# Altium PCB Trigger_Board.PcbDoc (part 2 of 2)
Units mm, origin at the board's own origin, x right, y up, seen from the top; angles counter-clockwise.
Board outline 80 x 80 mm, 4 copper layers (Component Side, Signal Layer 1, Signal Layer 2, Bottom Layer), stack 0.651 mm thick; 190 components, 73 nets, 468 pads, 398 vias.
Unrouted connection lines stored in the file: 444.
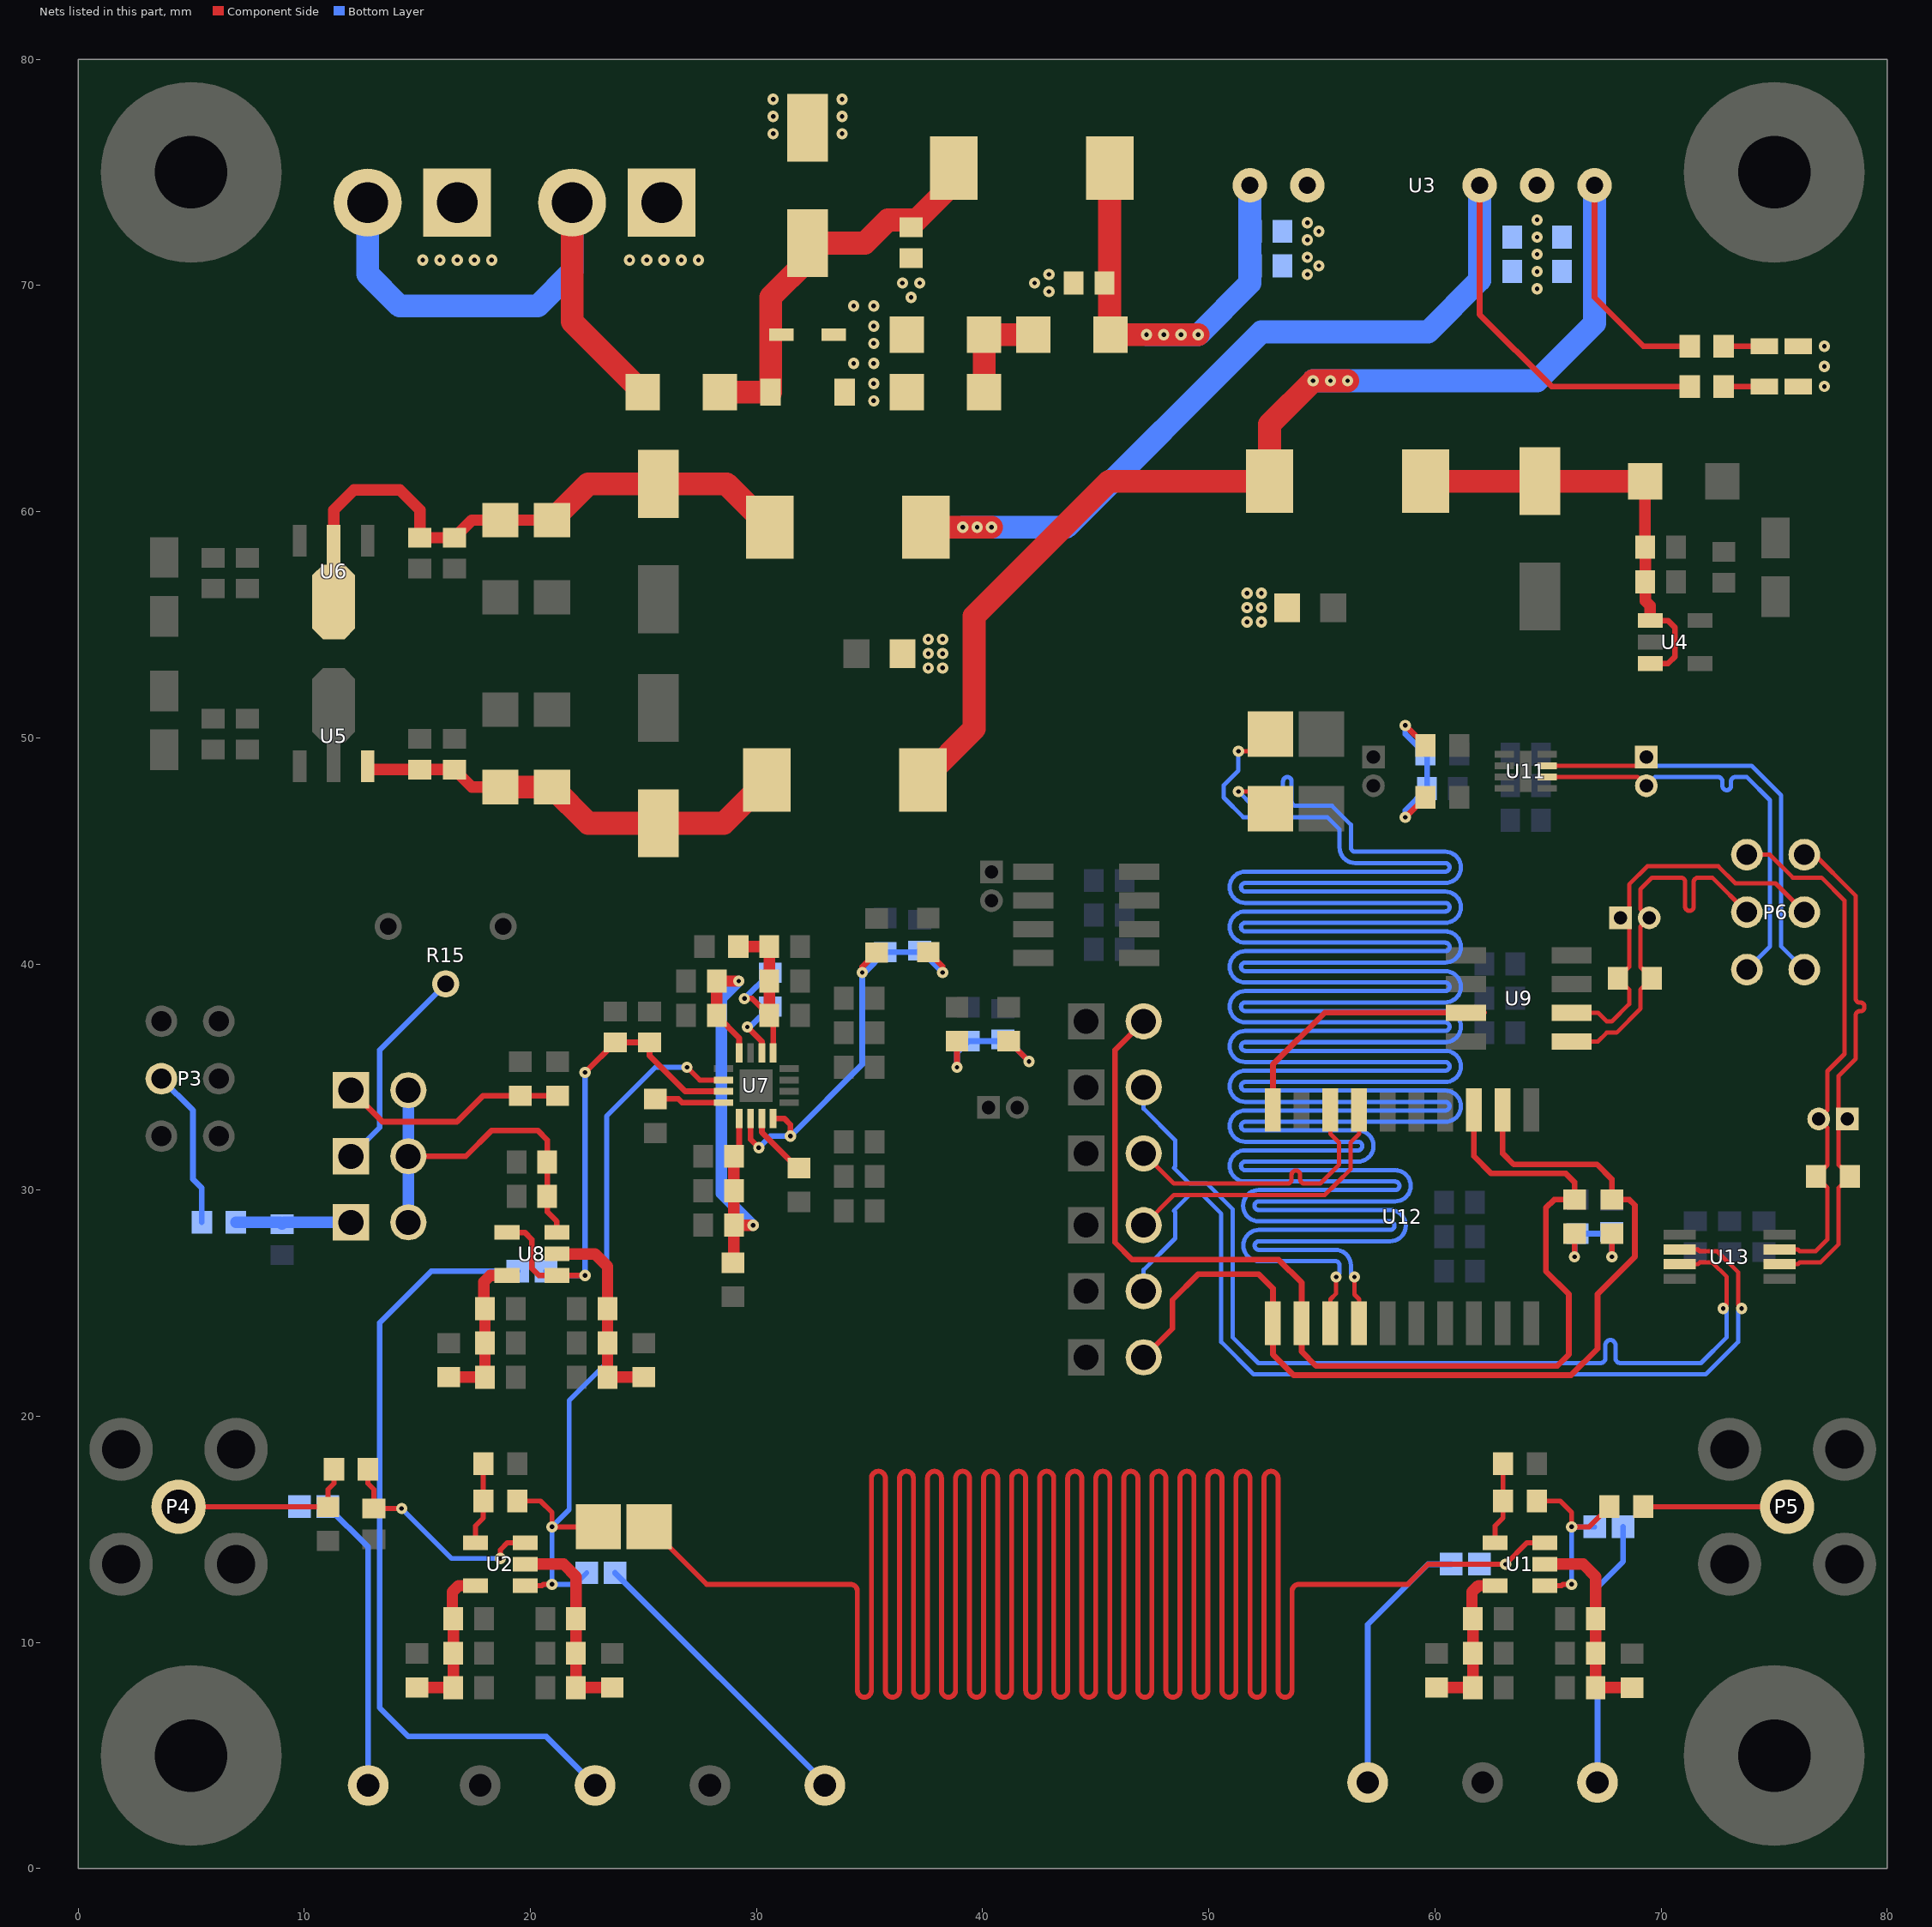
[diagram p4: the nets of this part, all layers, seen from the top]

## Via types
v1: diameter 0.5, hole 0.2, Component Side to Bottom Layer, 398 vias

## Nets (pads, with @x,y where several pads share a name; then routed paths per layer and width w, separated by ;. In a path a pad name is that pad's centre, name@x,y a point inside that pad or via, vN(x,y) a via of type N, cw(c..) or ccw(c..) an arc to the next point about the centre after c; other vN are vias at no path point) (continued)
DIn_N: J17.1 U12.4 | length 198.8
  Component Side w0.19: v1(51.308,47.625) 51.961,47.625 J17.1@52.723,46.863 ; v1(56.436,26.162) 56.436,25.381 56.642,25.174 U12.4@56.642,24.117
  Bottom Layer w0.19: v1(51.308,47.625) 51.943,46.99 53.213,46.99 ccw(c53.213,47.056) 53.279,47.056 53.279,48.073 cw(c53.469,48.073) 53.469,48.263 cw(c53.469,48.073) 53.659,48.073 53.659,47.18 ccw(c53.849,47.18) 53.849,46.99 54.039,46.99 54.229,46.99 55.444,46.99 56.281,46.153 56.281,45.15 ccw(c56.471,45.15) 56.471,44.96 60.452,44.96 cw(c60.452,44.27) 61.142,44.27 cw(c60.452,44.27) 60.452,43.58 51.61,43.58 ccw(c51.61,43.39) 51.42,43.39 ccw(c51.61,43.39) 51.61,43.2 60.452,43.2 cw(c60.452,42.51) 61.142,42.51 cw(c60.452,42.51) 60.452,41.82 51.61,41.82 ccw(c51.61,41.63) 51.42,41.63 ccw(c51.61,41.63) 51.61,41.44 60.452,41.44 cw(c60.452,40.75) 61.142,40.75 cw(c60.452,40.75) 60.452,40.06 51.61,40.06 ccw(c51.61,39.87) 51.42,39.87 ccw(c51.61,39.87) 51.61,39.68 60.452,39.68 cw(c60.452,38.99) 61.142,38.99 cw(c60.452,38.99) 60.452,38.3 51.61,38.3 ccw(c51.61,38.11) 51.42,38.11 ccw(c51.61,38.11) 51.61,37.92 60.452,37.92 cw(c60.452,37.23) 61.142,37.23 cw(c60.452,37.23) 60.452,36.54 51.61,36.54 ccw(c51.61,36.35) 51.42,36.35 ccw(c51.61,36.35) 51.61,36.16 60.452,36.16 cw(c60.452,35.47) 61.142,35.47 cw(c60.452,35.47) 60.452,34.78 51.61,34.78 ccw(c51.61,34.59) 51.42,34.59 ccw(c51.61,34.59) 51.61,34.4 60.452,34.4 cw(c60.452,33.71) 61.142,33.71 cw(c60.452,33.71) 60.452,33.02 51.61,33.02 ccw(c51.61,32.83) 51.42,32.83 ccw(c51.61,32.83) 51.61,32.64 56.59,32.64 cw(c56.59,31.95) 57.28,31.95 cw(c56.59,31.95) 56.59,31.26 51.61,31.26 ccw(c51.61,31.07) 51.42,31.07 ccw(c51.61,31.07) 51.61,30.88 58.233,30.88 cw(c58.233,30.19) 58.923,30.19 cw(c58.233,30.19) 58.233,29.5 52.205,29.5 ccw(c52.205,29.31) 52.015,29.31 ccw(c52.205,29.31) 52.205,29.12 58.016,29.12 cw(c58.016,28.43) 58.706,28.43 cw(c58.016,28.43) 58.016,27.74 52.215,27.74 ccw(c52.215,27.55) 52.025,27.55 ccw(c52.215,27.55) 52.215,27.36 55.591,27.36 cw(c55.591,26.67) 56.281,26.67 56.281,26.317 v1(56.436,26.162)
DIn_P: J14.1 U12.3 | length 198.8
  Component Side w0.19: v1(51.308,49.403) 51.961,49.403 J14.1@52.723,50.165 ; U12.3@55.372,24.117 55.372,25.174 55.626,25.428 v1(55.626,26.162)
  Bottom Layer w0.19: v1(51.308,49.403) 51.308,48.551 50.653,47.896 50.653,47.354 51.517,46.49 55.237,46.49 55.781,45.946 55.781,45.15 ccw(c56.471,45.15) 56.471,44.46 60.452,44.46 cw(c60.452,44.27) 60.642,44.27 cw(c60.452,44.27) 60.452,44.08 51.61,44.08 ccw(c51.61,43.39) 50.92,43.39 ccw(c51.61,43.39) 51.61,42.7 60.452,42.7 cw(c60.452,42.51) 60.642,42.51 cw(c60.452,42.51) 60.452,42.32 51.61,42.32 ccw(c51.61,41.63) 50.92,41.63 ccw(c51.61,41.63) 51.61,40.94 60.452,40.94 cw(c60.452,40.75) 60.642,40.75 cw(c60.452,40.75) 60.452,40.56 51.61,40.56 ccw(c51.61,39.87) 50.92,39.87 ccw(c51.61,39.87) 51.61,39.18 60.452,39.18 cw(c60.452,38.99) 60.642,38.99 cw(c60.452,38.99) 60.452,38.8 51.61,38.8 ccw(c51.61,38.11) 50.92,38.11 ccw(c51.61,38.11) 51.61,37.42 60.452,37.42 cw(c60.452,37.23) 60.642,37.23 cw(c60.452,37.23) 60.452,37.04 51.61,37.04 ccw(c51.61,36.35) 50.92,36.35 ccw(c51.61,36.35) 51.61,35.66 60.452,35.66 cw(c60.452,35.47) 60.642,35.47 cw(c60.452,35.47) 60.452,35.28 51.61,35.28 ccw(c51.61,34.59) 50.92,34.59 ccw(c51.61,34.59) 51.61,33.9 60.452,33.9 cw(c60.452,33.71) 60.642,33.71 cw(c60.452,33.71) 60.452,33.52 51.61,33.52 ccw(c51.61,32.83) 50.92,32.83 ccw(c51.61,32.83) 51.61,32.14 56.59,32.14 cw(c56.59,31.95) 56.78,31.95 cw(c56.59,31.95) 56.59,31.76 51.61,31.76 ccw(c51.61,31.07) 50.92,31.07 ccw(c51.61,31.07) 51.61,30.38 58.233,30.38 cw(c58.233,30.19) 58.423,30.19 cw(c58.233,30.19) 58.233,30 52.205,30 ccw(c52.205,29.31) 51.515,29.31 ccw(c52.205,29.31) 52.205,28.62 58.016,28.62 cw(c58.016,28.43) 58.206,28.43 cw(c58.016,28.43) 58.016,28.24 52.215,28.24 ccw(c52.215,27.55) 51.525,27.55 ccw(c52.215,27.55) 52.215,26.86 55.591,26.86 cw(c55.591,26.67) 55.781,26.67 55.781,26.317 v1(55.626,26.162)
DOut_N: J12.2 U12.17 | length 12.9
  Component Side w0.19: J12.2@47.117,28.448 48.455,29.786 55.131,29.786 55.658,30.313 56.257,30.912 56.257,32.099 56.642,32.484 U12.17@56.642,33.541
DOut_P: J13.2 U12.18 | length 12.9
  Component Side w0.19: J13.2@47.117,31.623 48.455,30.285 53.467,30.285 ccw(c53.467,30.475) 53.657,30.475 53.657,30.673 cw(c53.847,30.673) 53.847,30.863 cw(c53.847,30.673) 54.037,30.673 54.037,30.475 ccw(c54.227,30.475) 54.227,30.285 54.923,30.285 55.757,31.119 55.757,32.099 55.372,32.484 U12.18@55.372,33.541
EXT_threshold: C72.2 J8.1 L12.2 | length 5.2
  Bottom Layer w0.508: L12.2@6.973,28.575 8.935,28.575 C72.2@9.017,28.493 9.099,28.575 J8.1@12.065,28.575
Full_N: P6.6 R23.2 TP14.2 U13.3 | length 23.5
  Component Side w0.19: P6.6@73.787,44.831 74.803,44.831 75.819,43.815 77.089,43.815 78.105,42.799 78.105,36.017 77.347,35.259 77.347,33.532 TP14.2@76.962,33.147 77.347,32.762 77.347,31.107 R23.2@76.847,30.607 77.347,30.107 77.347,27.817 76.831,27.301 76.119,27.301 76.044,27.376 U13.3@75.237,27.376
Full_P: P6.5 R23.1 TP14.1 U13.2 | length 22.6
  Component Side w0.19: U13.2@75.237,26.726 76.044,26.726 76.119,26.801 77.038,26.801 77.189,26.951 77.847,27.61 77.847,30.107 R23.1@78.347,30.607 77.847,31.107 77.847,33.147 77.847,35.052 78.605,35.81 78.605,37.719 78.605,37.74 cw(c78.776,37.74) 78.776,37.911 78.816,37.911 ccw(c78.816,38.082) 78.987,38.082 78.987,38.12 ccw(c78.816,38.12) 78.816,38.291 78.776,38.291 cw(c78.776,38.462) 78.605,38.462 78.605,38.481 78.605,43.006 78.459,43.153 76.78,44.831 P6.5@76.327,44.831
GND: C14.1 C15.1 C27.2 C28.2 D3.2 D4.1 R9.1 R10.1 U3.6
  other v1: 37.592,53.086 38.227,53.086 37.592,53.721 38.227,53.721 37.592,54.356 38.227,54.356 51.689,55.118 52.324,55.118 51.689,55.753 52.324,55.753 51.689,56.388 52.324,56.388 77.216,65.532 77.216,66.421 77.216,67.31 64.516,69.85 64.516,70.612 64.516,71.374 64.516,72.136 64.516,72.898
HYS: R21.1 U7.14 | length 2.8
  Component Side w0.254: v1(29.591,37.211) 30.234,36.568 U7.14@30.234,36.068
  Bottom Layer w0.254: v1(29.591,37.211) 29.706,37.211 R21.1@30.607,38.112
IGND: C16.2 C17.1 C18.1 C19.1 C20.1 C29.1 C30.1 D1.1 D2.1 P1.1 P2.1 U3.2
  other v1: 35.179,64.897 35.179,65.659 34.29,66.548 35.179,66.548 35.179,67.437 35.179,68.199 34.29,69.088 35.179,69.088 36.83,69.469 42.926,69.723 36.449,70.104 37.211,70.104 42.291,70.104 42.926,70.485 54.356,70.485 54.864,70.866 15.24,71.12 16.002,71.12 16.764,71.12 17.526,71.12 18.288,71.12 24.384,71.12 25.146,71.12 25.908,71.12 26.67,71.12 27.432,71.12 54.356,71.247 54.356,72.009 54.864,72.39 54.356,72.771 30.734,76.708 33.782,76.708 30.734,77.47 33.782,77.47 30.734,78.232 33.782,78.232
LogD0_N: J10.2 R29.1 U12.1 U12.12 | length 42.6
  Component Side w0.254: J10.2@47.117,22.606 48.387,23.876 48.387,25.146 49.53,26.289 52.197,26.289 52.832,25.654 U12.1@52.832,24.117 52.832,22.733 53.744,21.821 66.017,21.821 67.183,22.987 67.183,25.4 68.834,27.051 68.834,29.337 68.592,29.579 R29.1@67.818,29.579 67.818,30.48 67.16,31.138 63.477,31.138 62.992,31.623 U12.12@62.992,33.541
LogD0_P: J11.2 R28.1 U12.2 U12.13 | length 50.7
  Component Side w0.254: J11.2@47.117,37.465 45.847,36.195 45.847,27.686 46.609,26.924 53.086,26.924 54.102,25.908 U12.2@54.102,24.117 54.102,22.86 54.737,22.225 65.405,22.225 65.913,22.733 65.913,25.4 64.897,26.416 64.897,29.21 65.266,29.579 R28.1@66.167,29.579 66.167,30.353 65.786,30.734 62.484,30.734 61.722,31.496 U12.13@61.722,33.541
NetC1_1: C1.1 C3.1 C5.1 L1.1 U1.5 | length 7
  Component Side w0.508: L1.1@60.071,8.013 60.083,8.001 C1.1@61.677,8.001 C3.1@61.677,9.525 C5.1@61.677,11.049 ; C5.1@61.632,11.049 61.632,12.229 61.915,12.512 U1.5@62.654,12.512
NetC2_1: C2.1 C4.1 C6.1 L2.1 U2.5 | length 6.9
  Component Side w0.508: L2.1@15.031,8.013 C2.1@16.58,8.013 ; C6.1@16.547,11.049 16.547,12.229 16.83,12.512 U2.5@17.569,12.512 ; C2.1@16.592,8.001 C4.1@16.592,9.525 C6.1@16.592,11.049
NetC7_1: C7.1 C9.1 C10.1 L3.2 U2.2 | length 9
  Component Side w0.508: U2.2@19.769,13.462 21.463,13.462 22.016,12.909 C7.1@22.016,11.049 C9.1@22.016,9.525 C10.1@22.016,8.001 23.61,8.001 L3.2@23.622,8.013
NetC8_2: C8.2 R3.2 U2.3 | length 10
  Component Side w0.22: R3.2@12.815,17.653 12.815,17.03 13.081,16.764 C8.2@13.081,15.92 v1(14.306,15.92) ; v1(18.669,13.716) 18.669,14.097 18.984,14.412 U2.3@19.769,14.412
  Bottom Layer w0.22: v1(14.306,15.92) 16.51,13.716 v1(18.669,13.716)
NetC11_1: C11.1 C12.1 C13.1 L4.2 U1.2 | length 9
  Component Side w0.508: U1.2@64.854,13.462 66.548,13.462 67.101,12.909 C11.1@67.101,11.049 C12.1@67.101,9.525 C13.1@67.101,8.001 L4.2@68.707,8.001
NetC16_1: C16.1 C17.2 D1.2 D2.2 F1.2 L5.1 | length 17.7
  Component Side w1.016: F1.2@28.38,65.278 D1.2@30.623,65.278 30.623,67.818 30.623,69.485 32.258,71.12 C16.1@32.258,71.872 34.788,71.872 35.814,72.898 36.83,72.898 37.084,72.898 38.714,74.528 L5.1@38.714,75.184
NetC18_2: C18.2 C19.2 C20.2 L5.2 R8.2 U3.1 | length 20.8
  Component Side w1.016: L5.2@45.614,75.184 45.614,70.104 45.614,68.11 R8.2@45.652,68.072 ; R8.2@45.652,67.818 v1(47.244,67.818) v1(48.006,67.818) v1(48.768,67.818) v1(49.53,67.818)
  Bottom Layer w1.016: v1(47.244,67.818) v1(48.006,67.818) v1(48.768,67.818) v1(49.53,67.818) 51.816,70.104 51.816,70.866 51.816,72.39 U3.1@51.816,74.422
NetC21_1: C21.1 C22.2 C23.2 C24.2 L6.2 U4.1 U4.3 | length 19.7
  Component Side w0.254: U4.3@69.512,53.279 70.297,53.279 70.612,53.594 70.612,54.864 70.297,55.179 U4.1@69.512,55.179
  Component Side w0.508: C22.2@69.283,61.341 69.283,58.434 C23.2@69.297,58.42 C24.2@69.297,56.896 69.297,56.052 69.512,55.837 U4.1@69.512,55.179
  Component Side w1.016: L6.2@59.584,61.341 64.643,61.341 C22.2@69.283,61.341
NetC29_2: C29.2 C30.2 R8.1 | length 4.7
  Component Side w1.016: C29.2@40.064,65.278 C30.2@40.064,67.818 R8.1@42.232,67.818
NetC31_1: C31.1 C32.2 C33.2 C34.2 C35.2 L7.2 U5.3 | length 19.5
  Component Side w0.508: U5.3@12.803,48.735 12.942,48.596 C35.2@15.113,48.596 C34.2@16.637,48.596 17.413,47.82 C33.2@18.669,47.82
  Component Side w1.016: C33.2@18.669,47.82 C32.2@20.955,47.82 22.557,46.218 C31.1@25.654,46.218 28.544,46.218 L7.2@30.459,48.133
NetC39_2: C39.2 C40.2 C41.2 C42.2 C43.2 L8.2 U6.2 | length 24.6
  Component Side w0.508: U6.2@11.303,58.507 11.303,60.071 12.192,60.96 14.224,60.96 15.113,60.071 C43.2@15.113,58.846 C42.2@16.637,58.846 17.413,59.622 C41.2@18.669,59.622 C40.2@20.955,59.622
  Component Side w1.016: C40.2@20.955,59.622 22.557,61.224 C39.2@25.654,61.224 28.671,61.224 L8.2@30.586,59.309
NetC47_1: C47.1 C48.1 C49.1 L9.1 U8.5 | length 7
  Component Side w0.508: L9.1@16.383,21.729 17.977,21.729 C47.1@17.989,21.717 C48.1@17.989,23.241 17.989,24.72 17.966,24.743 17.944,24.765 17.944,25.945 18.227,26.228 U8.5@18.966,26.228
NetC52_1: C52.1 C53.1 C57.1 L10.2 U8.2 | length 9
  Component Side w0.508: U8.2@21.166,27.178 22.86,27.178 23.413,26.625 C52.1@23.413,24.765 C53.1@23.413,23.241 C57.1@23.413,21.717 23.425,21.729 L10.2@25.019,21.729
NetC54_2: C54.2 R17.2 R18.2 R20.1 U7.6 U7.8 | length 19.7
  Component Side w0.254: U7.6@29.734,33.168 29.734,32.242 v1(30.099,31.877) ; U7.8@30.734,33.168 31.221,33.168 31.496,32.893 v1(31.496,32.385) ; v1(34.671,39.624) 34.671,39.872 R17.2@35.306,40.507 ; R18.2@37.592,40.525 38.227,39.89 v1(38.227,39.624)
  Bottom Layer w0.254: v1(30.099,31.877) 30.607,32.385 v1(31.496,32.385) 34.671,35.56 v1(34.671,39.624) 34.786,39.624 R20.1@35.687,40.525 37.141,40.525 C54.2@37.211,40.595 37.256,40.595 v1(38.227,39.624)
NetC55_2: C55.2 C56.2 J6.2 J7.2 J8.2 U8.3 | length 16.9
  Component Side w0.254: J7.2@14.605,31.496 17.145,31.496 18.288,32.639 20.32,32.639 20.746,32.213 C55.2@20.746,31.242 C56.2@20.746,29.718 20.746,29.038 21.166,28.618 U8.3@21.166,28.128
  Bottom Layer w0.508: J8.2@14.605,28.575 J7.2@14.605,31.496 J6.2@14.605,34.417
NetC59_1: C59.1 C61.1 C63.1 C65.1 C67.1 L11.1 U7.5 U7.16 | length 23.6
  Component Side w0.254: C67.1@28.239,37.719 29.234,36.724 U7.16@29.234,36.068 ; C63.1@29.001,31.496 29.234,31.729 U7.5@29.234,33.168
  Component Side w0.508: C67.1@28.239,37.719 C65.1@28.239,39.243 v1(29.21,39.243) ; L11.1@28.956,26.785 29.001,26.83 C59.1@29.001,28.448 ; C63.1@29.001,31.496 C61.1@29.001,29.972 C59.1@29.001,28.448 ; v1(29.845,28.448) C59.1@29.001,28.448
  Bottom Layer w0.508: v1(29.21,39.243) 28.448,38.481 28.448,29.845 v1(29.845,28.448)
NetC69_1: C69.1 C70.1 C71.1 L13.2 R21.2 U7.13 | length 9.4
  Component Side w0.254: v1(29.464,38.469) 29.812,38.469 C69.1@30.562,37.719 30.734,37.547 U7.13@30.734,36.068 ; C69.1@30.734,37.637 C69.1@30.816,37.719
  Component Side w0.508: L13.2@29.198,40.767 C71.1@30.562,40.767 C70.1@30.562,39.243 C69.1@30.562,37.719
  Bottom Layer w0.254: v1(29.464,38.469) R21.2@30.607,39.612
  Bottom Layer w0.508: R21.2@30.468,39.612 R21.2@30.607,39.612
NetC88_2: C88.2 R24.2 R25.2 R30.1 | length 7.4
  Component Side w0.254: v1(58.686,46.482) R25.2@59.575,47.371 ; v1(58.686,50.546) R24.2@59.575,49.657
  Bottom Layer w0.254: v1(58.686,46.482) 58.686,46.793 C88.2@59.645,47.752 59.645,49.206 R30.1@59.575,49.276 58.686,50.165 v1(58.686,50.546)
NetC89_2: C89.2 R26.2 R27.2 R31.1 | length 6.9
  Component Side w0.254: v1(38.862,35.433) R26.2@38.862,36.588 ; R27.2@41.148,36.588 v1(42.049,35.687)
  Bottom Layer w0.254: v1(38.862,35.433) 38.862,36.08 R31.1@39.37,36.588 40.697,36.588 40.767,36.658 C89.2@40.894,36.658 41.078,36.658 v1(42.049,35.687)
NetC90_2: C90.2 R28.2 R29.2 R32.1 | length 5.8
  Component Side w0.254: v1(66.167,27.051) R28.2@66.167,28.079 ; v1(67.818,27.051) R29.2@67.818,28.079
  Bottom Layer w0.254: v1(66.167,27.051) 66.167,27.952 R32.1@66.294,28.079 67.748,28.079 C90.2@67.818,28.149 v1(67.818,27.051)
NetD3_1: D3.1 R11.2 | length 1.8
  Component Side w0.254: R11.2@72.759,67.31 D3.1@74.561,67.31
NetD4_2: D4.2 R12.2 | length 1.8
  Component Side w0.254: R12.2@72.759,65.532 D4.2@74.561,65.532
NetF1_1: F1.1 P1.2 P2.2 | length 26.1
  Component Side w1.016: P2.2@21.844,73.66 21.844,68.394 F1.1@24.96,65.278
  Bottom Layer w1.016: P1.2@12.804,73.66 12.804,70.508 14.224,69.088 20.32,69.088 21.844,70.612 P2.2@21.844,73.66
NetJ1_1: J1.1 J4.1 R1.2 U2.1 U7.2 | length 35.7
  Component Side w0.22: R1.2@19.48,16.195 R1.2@19.419,16.256 20.447,16.256 20.955,15.748 v1(20.955,15.113) J4.1@23.005,15.113 ; U2.1@19.83,12.573 U2.1@19.769,12.512 20.513,12.512 20.574,12.573 v1(20.955,12.573) ; v1@27.051,35.433 v1(26.924,35.433) 27.489,34.868 U7.2@28.534,34.868
  Bottom Layer w0.22: J1.1@22.489,13.081 21.981,12.573 v1(20.955,12.573) v1(20.955,15.113) 21.717,15.875 21.717,20.701 23.368,22.352 23.368,33.274 25.527,35.433 v1(26.924,35.433)
NetJ1_2: J1.2 TP1.1 | length 13.2
  Bottom Layer w0.254: J1.2@23.739,13.081 33.02,3.8 TP1.1@33.02,3.683
NetJ2_1: J2.1 J4.2 U1.3 | length 343.8
  Component Side w0.22: J4.2@25.255,15.113 27.795,12.573 33.274,12.573 33.528,12.573 33.838,12.573 34.148,12.573 cw(c34.148,12.263) 34.458,12.263 34.458,7.887 ccw(c34.768,7.887) 34.768,7.577 ccw(c34.768,7.887) 35.078,7.887 35.078,12.573 35.078,17.259 cw(c35.388,17.259) 35.388,17.569 cw(c35.388,17.259) 35.698,17.259 35.698,12.573 35.698,7.887 ccw(c36.008,7.887) 36.008,7.577 ccw(c36.008,7.887) 36.318,7.887 36.318,12.573 36.318,17.259 cw(c36.628,17.259) 36.628,17.569 cw(c36.628,17.259) 36.938,17.259 36.938,12.573 36.938,7.887 ccw(c37.248,7.887) 37.248,7.577 ccw(c37.248,7.887) 37.558,7.887 37.558,12.573 37.558,17.259 cw(c37.868,17.259) 37.868,17.569 cw(c37.868,17.259) 38.178,17.259 38.178,12.573 38.178,7.887 ccw(c38.488,7.887) 38.488,7.577 ccw(c38.488,7.887) 38.798,7.887 38.798,12.573 38.798,17.259 cw(c39.108,17.259) 39.108,17.569 cw(c39.108,17.259) 39.418,17.259 39.418,12.573 39.418,7.887 ccw(c39.728,7.887) 39.728,7.577 ccw(c39.728,7.887) 40.038,7.887 40.038,12.573 40.038,17.259 cw(c40.348,17.259) 40.348,17.569 cw(c40.348,17.259) 40.658,17.259 40.658,12.573 40.658,7.887 ccw(c40.968,7.887) 40.968,7.577 ccw(c40.968,7.887) 41.278,7.887 41.278,12.573 41.278,17.259 cw(c41.588,17.259) 41.588,17.569 cw(c41.588,17.259) 41.898,17.259 41.898,12.573 41.898,7.887 ccw(c42.208,7.887) 42.208,7.577 ccw(c42.208,7.887) 42.518,7.887 42.518,12.573 42.518,17.259 cw(c42.828,17.259) 42.828,17.569 cw(c42.828,17.259) 43.138,17.259 43.138,12.573 43.138,7.887 ccw(c43.448,7.887) 43.448,7.577 ccw(c43.448,7.887) 43.758,7.887 43.758,12.573 43.758,17.259 cw(c44.068,17.259) 44.068,17.569 cw(c44.068,17.259) 44.378,17.259 44.378,12.573 44.378,7.887 ccw(c44.688,7.887) 44.688,7.577 ccw(c44.688,7.887) 44.998,7.887 44.998,12.573 44.998,17.259 cw(c45.308,17.259) 45.308,17.569 cw(c45.308,17.259) 45.618,17.259 45.618,12.573 45.618,7.887 ccw(c45.928,7.887) 45.928,7.577 ccw(c45.928,7.887) 46.238,7.887 46.238,12.573 46.238,17.259 cw(c46.548,17.259) 46.548,17.569 cw(c46.548,17.259) 46.858,17.259 46.858,12.573 46.858,7.887 ccw(c47.168,7.887) 47.168,7.577 ccw(c47.168,7.887) 47.478,7.887 47.478,12.573 47.478,17.259 cw(c47.788,17.259) 47.788,17.569 cw(c47.788,17.259) 48.098,17.259 48.098,12.573 48.098,7.887 ccw(c48.408,7.887) 48.408,7.577 ccw(c48.408,7.887) 48.718,7.887 48.718,12.573 48.718,17.259 cw(c49.028,17.259) 49.028,17.569 cw(c49.028,17.259) 49.338,17.259 49.338,12.573 49.338,7.887 ccw(c49.648,7.887) 49.648,7.577 ccw(c49.648,7.887) 49.958,7.887 49.958,12.573 49.958,17.259 cw(c50.268,17.259) 50.268,17.569 cw(c50.268,17.259) 50.578,17.259 50.578,12.573 50.578,7.887 ccw(c50.888,7.887) 50.888,7.577 ccw(c50.888,7.887) 51.198,7.887 51.198,12.573 51.198,17.259 cw(c51.508,17.259) 51.508,17.569 cw(c51.508,17.259) 51.818,17.259 51.818,12.573 51.818,7.887 ccw(c52.128,7.887) 52.128,7.577 ccw(c52.128,7.887) 52.438,7.887 52.438,12.573 52.438,17.259 cw(c52.748,17.259) 52.748,17.569 cw(c52.748,17.259) 53.058,17.259 53.058,12.573 53.058,7.887 ccw(c53.368,7.887) 53.368,7.577 ccw(c53.368,7.887) 53.678,7.887 53.678,12.263 cw(c53.988,12.263) 53.988,12.573 54.356,12.573 58.801,12.573 59.69,13.462 v1(63.119,13.462) 64.069,14.412 U1.3@64.854,14.412
  Bottom Layer w0.22: J2.1@61.966,13.462 v1(63.119,13.462)
NetJ2_2: J2.2 TP2.1 | length 11.8
  Bottom Layer w0.254: TP2.1@57.023,3.81 57.023,10.795 59.69,13.462 J2.2@60.716,13.462
NetJ3_1: J3.1 P4.1 R3.1 R5.2 | length 13.7
  Component Side w0.22: P4.1@4.445,16.002 11.037,16.002 R5.2@11.049,15.99 11.049,16.764 11.315,17.03 R3.1@11.315,17.653
  Bottom Layer w0.22: P4.1@4.445,16.002 J3.1@9.789,16.002
NetJ3_2: J3.2 TP3.1 | length 13.1
  Bottom Layer w0.254: J3.2@11.039,16.002 12.827,14.214 TP3.1@12.827,3.683
NetJ5_1: J5.1 TP4.1 | length 11.8
  Bottom Layer w0.254: TP4.1@67.183,3.81 67.183,12.446 68.316,13.579 J5.1@68.316,15.113
NetJ5_2: J5.2 R2.2 R4.1 U1.1 | length 9.2
  Component Side w0.22: R2.2@64.504,16.256 65.532,16.256 66.04,15.748 v1(66.04,15.113) 66.814,15.113 R4.1@67.703,16.002 ; U1.1@64.854,12.512 65.598,12.512 65.659,12.573 v1(66.04,12.573)
  Bottom Layer w0.22: v1(66.04,12.573) v1(66.04,15.113) J5.2@67.066,15.113
NetJ6_1: J6.1 R13.1 R14.2 | length 10.2
  Component Side w0.254: J6.1@12.065,34.417 13.462,33.02 16.752,33.02 17.907,34.175 R13.1@19.558,34.175 R14.2@21.209,34.175
NetJ7_1: J7.1 R15.2 | length 9.4
  Bottom Layer w0.254: J7.1@12.065,31.496 13.335,32.766 13.335,36.195 R15.2@16.256,39.116
NetJ9_1: J9.1 TP9.1 | length 35
  Bottom Layer w0.254: J9.1@19.441,26.416 15.621,26.416 13.335,24.13 13.335,7.112 14.605,5.842 20.701,5.842 TP9.1@22.86,3.683
NetL12_1: L12.1 P3.3 | length 7.1
  Bottom Layer w0.254: P3.3@3.683,34.925 5.08,33.528 5.08,30.48 5.473,30.087 L12.1@5.473,28.575
NetP5_1: P5.1 R4.2 | length 6.4
  Component Side w0.22: R4.2@69.203,16.002 P5.1@75.565,16.002
NetR1_1: R1.1 R6.2 U2.4 | length 3.8
  Component Side w0.22: U2.4@17.569,14.412 17.569,15.156 17.919,15.506 R1.1@17.919,16.256 R6.2@17.919,17.907 R6.2@17.919,18.034
NetR2_1: R2.1 R7.2 U1.4 | length 3.6
  Component Side w0.22: U1.4@62.654,14.412 62.654,15.156 63.004,15.506 R2.1@63.004,16.256 R7.2@63.004,17.907
NetR16_2: R16.2 U7.4 | length 3
  Component Side w0.254: R16.2@25.654,34.024 25.666,34.036 26.543,34.036 26.711,33.868 U7.4@28.534,33.868
NetR19_2: R19.2 U7.7 | length 2.9
  Component Side w0.254: U7.7@30.23,33.164 U7.7@30.234,33.168 30.234,32.555 31.813,30.976 R19.2@31.877,30.976
nFull_N: J15.2 U13.6 | length 42.8
  Component Side w0.19: U13.6@70.813,27.376 71.62,27.376 71.696,27.301 72.47,27.301 73.398,26.373 73.398,24.92 v1(73.553,24.765)
  Bottom Layer w0.19: J15.2@47.117,25.527 47.117,26.475 48.512,27.87 48.512,29.026 48.451,29.087 49.149,29.786 49.716,29.786 50.546,28.956 50.546,23.288 51.982,21.852 71.962,21.852 73.252,23.141 73.398,23.288 73.398,24.638 73.525,24.765 v1(73.553,24.765)
nFull_P: J16.2 U13.7 | length 42.8
  Component Side w0.19: U13.7@70.813,26.726 71.62,26.726 71.696,26.801 72.263,26.801 72.898,26.166 72.898,24.92 v1(72.743,24.765)
  Bottom Layer w0.19: J16.2@47.117,34.544 47.117,33.596 48.512,32.201 48.512,31.045 48.451,30.984 49.149,30.285 49.924,30.285 51.046,29.163 51.046,23.495 52.189,22.352 67.31,22.352 ccw(c67.31,22.574) 67.532,22.574 67.532,23.149 cw(c67.754,23.149) 67.754,23.371 cw(c67.754,23.149) 67.976,23.149 67.976,22.574 ccw(c68.198,22.574) 68.198,22.352 68.58,22.352 71.755,22.352 72.898,23.495 72.898,24.638 72.771,24.765 v1(72.743,24.765)
Ready_N: P6.4 R22.1 TP10.2 U9.1 | length 18.3
  Component Side w0.19: U9.1@65.586,36.576 U9.1@66.04,36.576 67.206,36.576 67.591,36.961 68.025,36.961 69.084,38.02 69.084,38.87 R22.1@69.584,39.37 69.084,39.87 69.084,41.652 TP10.2@69.469,42.037 69.084,42.422 69.084,43.307 69.592,43.815 70.868,43.815 cw(c70.868,43.625) 71.058,43.625 71.058,42.536 ccw(c71.248,42.536) 71.248,42.346 ccw(c71.248,42.536) 71.438,42.536 71.438,43.625 cw(c71.628,43.625) 71.628,43.815 72.263,43.815 P6.4@73.787,42.291
Ready_P: P6.3 R22.2 TP10.1 U9.2 | length 18.4
  Component Side w0.19: U9.2@65.586,37.846 U9.2@66.04,37.846 67.206,37.846 67.591,37.461 67.818,37.461 68.584,38.227 68.584,38.87 R22.2@68.084,39.37 68.584,39.87 68.584,41.652 TP10.1@68.199,42.037 68.584,42.422 68.584,43.514 69.385,44.315 72.525,44.315 73.279,43.561 75.057,43.561 P6.3@76.327,42.291
Ready_single: U9.7 U12.20 | length 12.1
  Component Side w0.254: U12.20@52.832,33.541 52.832,35.56 55.118,37.846 U9.7@61.36,37.846 ; U9.7@61.541,37.846 U9.7@62.176,37.846
TRG_out_N: P6.2 TP11.2 U11.6 | length 19.3
  Component Side w0.19: U11.6@64.958,48.264 68.957,48.264 TP11.2@69.342,47.879
  Bottom Layer w0.19: TP11.2@69.342,47.879 69.723,48.26 72.136,48.26 72.326,48.26 72.516,48.26 cw(c72.516,48.07) 72.706,48.07 72.706,47.871 ccw(c72.896,47.871) 72.896,47.681 ccw(c72.896,47.871) 73.086,47.871 73.086,48.07 cw(c73.276,48.07) 73.276,48.26 73.791,48.26 74.807,47.244 74.807,40.771 P6.2@73.787,39.751
TRG_out_P: P6.1 TP11.1 U11.7 | length 19.3
  Component Side w0.19: U11.7@64.958,48.764 68.957,48.764 TP11.1@69.342,49.149
  Bottom Layer w0.19: TP11.1@69.342,49.149 69.731,48.76 73.998,48.76 75.307,47.451 75.307,40.771 P6.1@76.327,39.751
TRG_threshold: C50.2 C51.2 J9.2 U7.3 U8.1 U8.4 | length 23.7
  Component Side w0.254: U8.4@18.966,28.128 19.751,28.128 20.066,27.813 20.066,26.543 20.381,26.228 U8.1@21.166,26.228 v1(22.418,26.228) ; v1(22.418,35.2) C50.2@23.749,36.531 C51.2@25.273,36.531 25.273,35.941 26.846,34.368 U7.3@28.534,34.368
  Bottom Layer w0.254: J9.2@20.691,26.416 21.336,26.416 21.524,26.228 v1(22.418,26.228) v1(22.418,35.2)
VCC: C14.2 C15.2 L6.1 L7.1 R11.1 U3.7 | length 60.1
  Component Side w0.254: U3.7@67.056,74.422 67.056,69.469 69.215,67.31 R11.1@71.259,67.31
  Component Side w1.016: L7.1@37.359,48.133 39.624,50.398 39.624,55.372 45.593,61.341 L6.1@52.684,61.341 52.684,63.86 v1(54.61,65.786) v1(55.372,65.786) v1(56.134,65.786)
  Bottom Layer w1.016: v1(54.61,65.786) v1(55.372,65.786) v1(56.134,65.786) 64.516,65.786 67.056,68.326 67.056,70.612 67.056,72.136 U3.7@67.056,74.422
VDD: C27.1 C28.1 L8.1 R12.1 U3.5 | length 50.8
  Component Side w0.254: U3.5@61.976,74.422 61.976,68.707 65.151,65.532 R12.1@71.259,65.532
  Component Side w1.016: L8.1@37.486,59.309 v1(39.116,59.309) v1(39.751,59.309) v1(40.386,59.309)
  Bottom Layer w1.016: v1(39.116,59.309) v1(39.751,59.309) v1(40.386,59.309) 43.688,59.309 52.324,67.945 59.69,67.945 61.976,70.231 61.976,70.612 61.976,72.136 U3.5@61.976,74.422
pads on no net: U4.4 U9.3 U9.4 U9.6 U11.1 U11.4 U12.5

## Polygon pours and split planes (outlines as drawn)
IGND on Bottom Layer "BOT-IGND" (solid, remove dead copper, shelved, pour order 4): 0,63.881 0,80 57.785,80 57.785,66.421 44.831,66.421 42.291,63.881
GND on Bottom Layer "BOT-DGND" (solid, remove dead copper, shelved, pour order 18): 35.941,43.815 37.084,43.815 40.259,46.99 40.259,54.61 53.975,54.61 53.975,64.516 80,64.516 80,80 59.065,80 59.055,80.01 59.055,68.199 52.324,68.199 50.292,66.167 45.212,66.167 42.545,63.5 35.941,63.5
AGND on Bottom Layer "BOT-AGND" (solid, shelved, pour order 12): 34.925,63.5 34.925,43.815 33.147,43.815 33.147,37.084 28.956,37.084 28.956,32.244 29.845,32.244 29.845,32.131 29.845,20.447 79.996,20.447 80,0 0,0 0,62.738 0,63.5
DGND on Bottom Layer "BOT-DGND" (solid, remove dead copper, shelved, pour order 20): 30.099,20.701 30.099,32.512 29.21,32.512 29.21,36.83 33.274,36.83 33.274,43.561 37.338,43.561 40.513,46.736 40.513,54.356 54.991,54.356 54.991,64.135 80,64.135 80,20.701
GND on Signal Layer 2 "Signal2-GND" (solid, remove dead copper, shelved, pour order 36): 35.941,43.815 37.084,43.815 40.259,46.99 40.259,54.61 53.975,54.61 53.975,64.516 80,64.516 80,80 59.065,80 59.055,80.01 59.055,68.072 52.324,68.072 50.419,66.167 45.212,66.167 42.545,63.5 35.941,63.5
IGND on Signal Layer 2 "Signal2-IGND" (solid, remove dead copper, shelved, pour order 44): 0,63.881 0,80 57.785,80 57.785,66.421 44.831,66.421 42.291,63.881
+3V3-D on Signal Layer 2 "Signal2-+3V3-D" (solid, remove dead copper, shelved, pour order 54): 30.099,20.701 30.099,32.512 29.21,32.512 29.21,36.83 33.274,36.83 33.274,43.561 37.338,43.561 40.513,46.736 40.513,54.356 54.991,54.356 54.991,64.135 80,64.135 80,20.701
-5V-A on Signal Layer 2 "Signal2--5V-A" (solid, shelved, pour order 62): 0,62.865 0.039,62.826 34.925,62.826 34.925,43.815 33.147,43.815 33.147,37.084 28.956,37.084 28.956,32.004 28.929,32.031 26.67,32.031 26.67,20.701 23.495,20.701 23.495,54.229 3.81,54.229 3.81,44.069 12.192,44.069 12.192,7.112 19.431,7.112 19.431,13.462 58.293,13.462 58.293,6.985 64.608,6.985 64.608,20.447 80,20.447 80,0 0,0
+5V-A on Signal Layer 2 "Signal2-+5V-A" (solid, shelved, pour order 64): 3.81,44.069 12.192,44.069 12.192,7.112 19.177,7.112 19.177,13.462 58.293,13.462 58.293,6.985 64.262,6.985 64.262,20.447 29.845,20.447 29.845,32.004 29.841,32 26.67,32 26.67,20.701 23.495,20.701 23.495,54.2 23.466,54.229 3.81,54.229
GND on Signal Layer 1 "Signal1-GND" (solid, remove dead copper, shelved, pour order 34): 35.941,43.815 37.084,43.815 40.259,46.99 40.259,54.61 53.975,54.61 53.975,64.516 80,64.516 80,80 59.065,80 59.055,80.01 59.055,68.072 52.324,68.072 50.419,66.167 45.212,66.167 42.545,63.5 35.941,63.5
IGND on Signal Layer 1 "Signal1-IGND" (solid, remove dead copper, shelved, pour order 40): 0,63.881 0,80 57.785,80 57.785,66.421 44.831,66.421 42.291,63.881
DGND on Signal Layer 1 "Signal1-DGND" (solid, remove dead copper, shelved, pour order 50): 30.109,20.701 30.109,32.512 29.22,32.512 29.22,36.83 33.274,36.83 33.274,43.561 37.348,43.561 40.523,46.736 40.523,54.356 55.001,54.356 55.001,64.135 80.01,64.135 80.01,20.701
AGND on Signal Layer 1 "Signal1-AGND" (solid, shelved, pour order 56): 34.925,63.5 34.925,43.815 33.147,43.815 33.147,37.084 28.956,37.084 28.956,32.244 29.845,32.244 29.845,32.131 29.845,20.447 79.996,20.447 80,0 0,0 0,62.738 -0.762,63.5
GND on Component Side "TOP-GND" (solid, remove dead copper, shelved, pour order 38): 35.941,43.815 37.084,43.815 40.259,46.99 40.259,54.61 53.975,54.61 53.975,64.516 80,64.516 80,80 59.065,80 59.055,80.01 59.055,68.072 52.324,68.072 50.419,66.167 45.212,66.167 42.545,63.5 35.941,63.5
IGND on Component Side "TOP-IGND" (solid, remove dead copper, shelved, pour order 46): 0,63.881 0,80 57.785,80 57.785,66.421 44.831,66.421 42.291,63.881
DGND on Component Side "TOP-DGND" (solid, remove dead copper, shelved, pour order 52): 30.099,20.701 30.099,32.512 29.21,32.512 29.21,36.83 33.274,36.83 33.274,43.561 37.338,43.561 40.513,46.736 40.513,54.356 54.991,54.356 54.991,64.135 80,64.135 80,20.701
AGND on Component Side "TOP-AGND" (solid, remove dead copper, shelved, pour order 58): 34.925,63.5 34.925,43.815 33.147,43.815 33.147,37.084 28.956,37.084 28.956,32.244 29.845,32.244 29.845,32.131 29.845,20.447 79.996,20.447 80,0 0,0 0,62.738 0,63.5

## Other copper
Signal Layer 2:
  pour cut-out: 47.879,44.45 49.276,44.45 49.276,43.688 47.879,43.688
  pour cut-out: 62.484,26.797 63.881,26.797 63.881,26.035 62.484,26.035
  pour cut-out: 65.405,50.038 66.802,50.038 66.802,49.276 65.405,49.276
  pour cut-out: 62.992,36.068 64.516,36.068 64.516,35.306 62.992,35.306
  pour cut-out: 73.914,26.416 74.676,26.416 74.676,25.654 73.914,25.654
  pour cut-out: 68.58,25.781 69.85,25.781 69.85,26.416 68.58,26.416

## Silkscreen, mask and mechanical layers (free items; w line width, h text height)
Top Overlay:
  lines w0.22: 35.306,2.667 54.737,2.667
  lines w0.254: 0.508,22.86 10.795,22.86 13.462,20.193 33.782,20.193 65.405,20.193 67.818,22.606 79.502,22.606 ; 9.398,22.86 9.398,8.636 11.049,6.985 28.194,6.985 ; 28.194,20.193 28.194,6.985 ; 37.592,34.671 37.592,33.655 38.608,32.639 38.608,20.193 ; 38.354,38.862 38.735,39.243 38.735,42.291 38.735,44.196 ; 40.259,54.483 50.927,54.483 ; 49.403,42.672 60.706,42.672 ; 57.023,20.193 57.023,6.985 ; 71.247,22.606 70.485,22.606 70.485,12.992 72.263,11.214 72.263,8.458 70.79,6.985 57.023,6.985 ; 79.375,51.689 59.182,51.689 56.388,54.483 50.927,54.483 ; 79.502,64.262 66.167,64.262 64.389,66.04 50.927,66.04 50.927,54.483 ; 28.194,6.985 57.023,6.985 ; 38.735,44.196 40.259,45.72 40.259,63.754 1.651,63.754 1.651,46.101 1.651,44.196 38.735,44.196
  text "PWR" at 73.66,68.453 h1.2
  text "Power +5V" at 9.271,65.024 h1.5
  text "Voltage Regulators" at 2.921,61.849 h0.9
  text "Analog" at 5.08,60.706 h0.9
  text "Voltage Reg. / Digital" at 79.629,54.356 h0.8 r90
  text "BUSY Logic" at 41.402,52.451 h1
  text "Busy Sellect" at 49.403,43.383 h1
  text "J10,J11-No / J15,J16-Fifo / J12,J13-Ready" at 49.403,38.354 h0.8
  text "Thr. setting" at 11.811,36.703 h0.8
  text "Fixed" at 17.018,32.512 h0.8 r90
  text "LVDS / Output" at 70.485,31.75 h1 r90
  text "Trim" at 18.034,29.718 h0.8 r90
  text "EXT" at 17.018,27.559 h0.8 r90
  text "Ext.Threshold / Input" at 0.381,23.876 h0.8
  text "Busy  / Sellect" at 43.053,23.622 h1 r90
  text "Trigger" at 30.226,20.574 h1.2
  text "Input Buffers" at 14.224,18.923 h0.9
  text "Out. Buffers" at 57.531,18.923 h0.9
  text "Signal Delay / t=2ns" at 28.575,15.748 h1.2
  text "Input" at 1.651,9.525 h1.2
  text "Output" at 72.771,9.525 h1.2
  text "Particle Physics DAQ Education Kit" at 35.179,2.921 h1.2
  text "Trigger Board" at 41.402,1.27 h0.9
  text "Input" at 11.176,0.888 h0.8
  text "GND" at 16.51,0.888 h1
  text "Thresh." at 20.32,0.888 h0.8
  text "GND" at 26.67,0.888 h1
  text "Buffer" at 30.988,0.888 h0.8
  text "Delay" at 55.372,0.888 h0.8
  text "GND" at 60.833,0.888 h1
  text "Output" at 65.405,0.888 h0.8
Bottom Overlay:
  lines w0.254: 50.673,25.908 50.673,32.258 50.673,45.466 61.341,45.466 61.341,33.02 59.055,30.734 59.055,25.908 50.673,25.908
  text "AND / Out" at 53.213,47.244 h0.8 r270
  text "Trigger / Out" at 70.757,45.847 h0.8 r270
  text "Comp. / Out" at 42.164,45.339 h0.8
  text "Ready / In" at 70.866,38.1 h0.8
  text "Delay / t=1.12ns" at 56.896,29.972 h1.2 r270
  text "AND / In" at 42.418,29.591 h0.8
  text "Full / In" at 79.629,29.21 h0.8
Mechanical 1:
  lines w2.4: -1.2,12.4 -1.2,-1.2 12.4,-1.2 ; -1.2,18.5 -1.2,36.7 ; -1.2,42.5 -1.2,60.7 ; -1.2,67.6 -1.2,81.2 12.4,81.2 ; 18.5,81.2 36.7,81.2 ; 19.3,-1.2 37.5,-1.2 ; 42.5,81.2 60.7,81.2 ; 43.3,-1.2 61.5,-1.2 ; 67.6,-1.2 81.2,-1.2 81.2,12.4 ; 67.6,81.2 81.2,81.2 81.2,67.6 ; 81.2,19.3 81.2,37.5 ; 81.2,43.3 81.2,61.5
